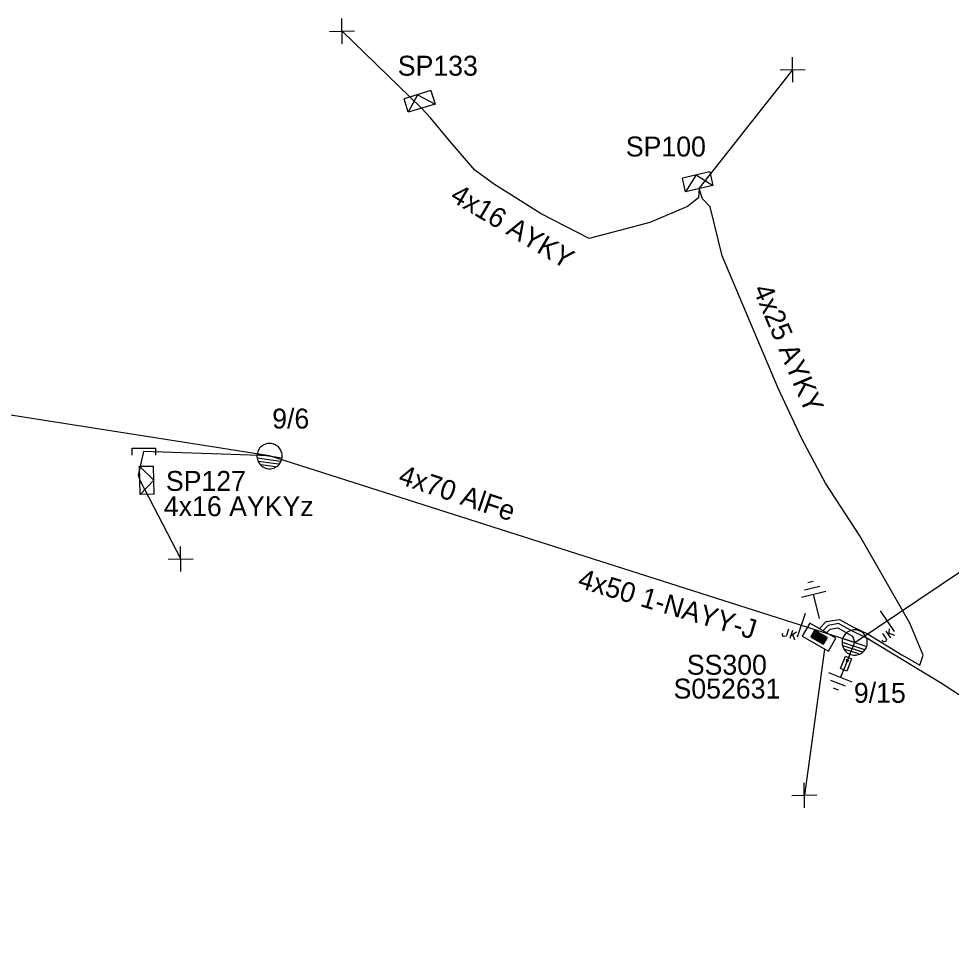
# Model space of a CAD drawing. Extents: x -762504 to -761250, y -1152974 to -1152253.
# Drawn here: x -761400.94 to -761354.44, y -1152566.54 to -1152520.81 of the extents above; entities that cross this region are included whole.
import ezdxf

# ---------------------------------------------------------------- set-up
doc = ezdxf.new("R2010")
doc.units = 0
for name, color, linetype in [('Vrstva 1', 7, 'Continuous'), ('Vrstva 12', 7, 'Continuous'), ('Vrstva 13', 7, 'Continuous'), ('Vrstva 15', 7, 'Continuous'), ('Vrstva 16', 7, 'Continuous'), ('Vrstva 18', 7, 'Continuous'), ('Vrstva 2', 7, 'Continuous'), ('Vrstva 28', 7, 'Continuous'), ('Vrstva 29', 7, 'Continuous'), ('Vrstva 30', 7, 'Continuous'), ('Vrstva 31', 7, 'Continuous'), ('Vrstva 33', 7, 'Continuous'), ('Vrstva 34', 7, 'Continuous'), ('Vrstva 5', 7, 'Continuous'), ('Vrstva 52', 7, 'Continuous'), ('Vrstva 54', 7, 'Continuous'), ('Vrstva 55', 7, 'Continuous'), ('Vrstva 59', 7, 'Continuous'), ('Vrstva 6', 7, 'Continuous')]:
    doc.layers.add(name, color=color, linetype=linetype)

msp = doc.modelspace()

# ---------------------------------------------------------------- linework, layer by layer
at = {"layer": 'Vrstva 1'}
msp.add_lwpolyline([(-761359.26, -1152551.93), (-761388.43, -1152542.63), (-761419.76, -1152537.7), (-761438.71, -1152534.5), (-761457.83, -1152530.5)], dxfattribs=at)
at = {"layer": 'Vrstva 13'}
for points in [[(-761395.3, -1152542.234), (-761394.119, -1152542.234)], [(-761395.3, -1152542.234), (-761395.3, -1152542.588)], [(-761394.119, -1152542.234), (-761394.119, -1152542.588)], [(-761387.805, -1152542.722), (-761387.8, -1152542.656), (-761387.801, -1152542.59), (-761387.809, -1152542.525), (-761387.824, -1152542.461), (-761387.845, -1152542.398), (-761387.873, -1152542.339), (-761387.907, -1152542.282), (-761387.946, -1152542.229), (-761387.991, -1152542.181), (-761388.041, -1152542.138), (-761388.095, -1152542.1), (-761388.153, -1152542.068), (-761388.214, -1152542.042), (-761388.277, -1152542.023), (-761388.342, -1152542.011), (-761388.407, -1152542.005), (-761388.473, -1152542.006), (-761388.539, -1152542.014), (-761388.603, -1152542.029), (-761388.665, -1152542.05), (-761388.725, -1152542.078), (-761388.781, -1152542.112), (-761388.834, -1152542.152), (-761388.882, -1152542.197), (-761388.925, -1152542.247), (-761388.963, -1152542.3), (-761388.995, -1152542.358), (-761389.021, -1152542.419), (-761389.04, -1152542.482), (-761389.053, -1152542.547), (-761389.059, -1152542.612), (-761389.058, -1152542.678), (-761389.05, -1152542.744), (-761389.035, -1152542.808), (-761389.013, -1152542.87), (-761388.985, -1152542.93), (-761388.951, -1152542.987), (-761388.912, -1152543.039), (-761388.867, -1152543.087), (-761388.817, -1152543.131), (-761388.763, -1152543.169), (-761388.705, -1152543.2), (-761388.645, -1152543.226), (-761388.581, -1152543.246), (-761388.517, -1152543.258), (-761388.451, -1152543.264), (-761388.385, -1152543.263), (-761388.32, -1152543.255), (-761388.255, -1152543.24), (-761388.193, -1152543.218), (-761388.133, -1152543.191), (-761388.077, -1152543.157), (-761388.024, -1152543.117), (-761387.976, -1152543.072), (-761387.933, -1152543.022), (-761387.895, -1152542.968), (-761387.863, -1152542.91), (-761387.837, -1152542.85), (-761387.818, -1152542.787), (-761387.805, -1152542.722)], [(-761389.054, -1152542.542), (-761387.807, -1152542.718)], [(-761389.05, -1152542.722), (-761387.89, -1152542.885)], [(-761388.982, -1152542.88), (-761387.979, -1152543.022)], [(-761388.866, -1152543.046), (-761388.145, -1152543.147)], [(-761358.661, -1152552.129), (-761358.644, -1152552.065), (-761358.633, -1152552), (-761358.63, -1152551.934), (-761358.633, -1152551.868), (-761358.644, -1152551.803), (-761358.661, -1152551.74), (-761358.684, -1152551.678), (-761358.714, -1152551.619), (-761358.75, -1152551.564), (-761358.792, -1152551.513), (-761358.838, -1152551.466), (-761358.89, -1152551.425), (-761358.945, -1152551.389), (-761359.004, -1152551.359), (-761359.065, -1152551.335), (-761359.129, -1152551.318), (-761359.194, -1152551.308), (-761359.26, -1152551.304), (-761359.326, -1152551.308), (-761359.391, -1152551.318), (-761359.454, -1152551.335), (-761359.516, -1152551.359), (-761359.575, -1152551.389), (-761359.63, -1152551.425), (-761359.681, -1152551.466), (-761359.728, -1152551.513), (-761359.769, -1152551.564), (-761359.805, -1152551.619), (-761359.835, -1152551.678), (-761359.859, -1152551.74), (-761359.876, -1152551.803), (-761359.886, -1152551.868), (-761359.89, -1152551.934), (-761359.886, -1152552), (-761359.876, -1152552.065), (-761359.859, -1152552.129), (-761359.835, -1152552.19), (-761359.805, -1152552.249), (-761359.769, -1152552.305), (-761359.728, -1152552.356), (-761359.681, -1152552.403), (-761359.63, -1152552.444), (-761359.575, -1152552.48), (-761359.516, -1152552.51), (-761359.455, -1152552.533), (-761359.391, -1152552.551), (-761359.326, -1152552.561), (-761359.26, -1152552.564), (-761359.194, -1152552.561), (-761359.129, -1152552.551), (-761359.065, -1152552.533), (-761359.003, -1152552.51), (-761358.945, -1152552.48), (-761358.89, -1152552.444), (-761358.838, -1152552.402), (-761358.792, -1152552.356), (-761358.75, -1152552.305), (-761358.714, -1152552.249), (-761358.684, -1152552.191), (-761358.661, -1152552.129)], [(-761359.886, -1152551.913), (-761358.772, -1152552.275)], [(-761359.859, -1152551.735), (-761358.661, -1152552.125)], [(-761359.848, -1152552.081), (-761358.883, -1152552.394)], [(-761359.762, -1152552.264), (-761359.069, -1152552.489)]]:
    msp.add_lwpolyline(points, dxfattribs=at)
at = {"layer": 'Vrstva 15'}
for points in [[(-761361.592, -1152548.943), (-761361.463, -1152548.911)], [(-761361.463, -1152548.911), (-761361.338, -1152548.88)], [(-761361.918, -1152549.668), (-761360.705, -1152549.366)], [(-761361.759, -1152549.309), (-761360.995, -1152549.118)], [(-761361.009, -1152550.73), (-761361.311, -1152549.517)], [(-761359.496, -1152552.525), (-761359.964, -1152553.684)], [(-761359.385, -1152553.918), (-761360.544, -1152553.45)], [(-761359.724, -1152554.115), (-761360.455, -1152553.82)], [(-761360.198, -1152554.263), (-761360.317, -1152554.215)], [(-761360.075, -1152554.313), (-761360.198, -1152554.263)]]:
    msp.add_lwpolyline(points, dxfattribs=at)
at = {"layer": 'Vrstva 16'}
for points in [[(-761359.261, -1152551.925), (-761359.655, -1152552.902)], [(-761359.965, -1152553.233), (-761359.717, -1152552.622)], [(-761359.717, -1152552.622), (-761359.412, -1152552.745)], [(-761359.655, -1152552.902), (-761359.664, -1152552.766)], [(-761359.412, -1152552.745), (-761359.659, -1152553.357)], [(-761359.655, -1152552.902), (-761359.555, -1152552.81)], [(-761359.659, -1152553.357), (-761359.965, -1152553.233)], [(-761359.814, -1152553.294), (-761359.963, -1152553.664)]]:
    msp.add_lwpolyline(points, dxfattribs=at)
at = {"layer": 'Vrstva 18'}
for points in [[(-761361.736, -1152550.482), (-761362.123, -1152551.671)], [(-761357.984, -1152550.345), (-761357.285, -1152551.381)], [(-761362.861, -1152551.571), (-761362.858, -1152551.514)], [(-761362.801, -1152551.626), (-761362.861, -1152551.571)], [(-761362.858, -1152551.514), (-761362.843, -1152551.468)], [(-761362.773, -1152551.635), (-761362.801, -1152551.626)], [(-761362.697, -1152551.624), (-761362.773, -1152551.635)], [(-761362.662, -1152551.578), (-761362.697, -1152551.624)], [(-761362.561, -1152551.269), (-761362.662, -1152551.578)], [(-761362.365, -1152551.333), (-761362.493, -1152551.727)], [(-761362.444, -1152551.577), (-761362.168, -1152551.397)], [(-761362.353, -1152551.518), (-761362.263, -1152551.801)], [(-761357.871, -1152551.48), (-761357.69, -1152551.749)], [(-761357.7, -1152551.364), (-761357.469, -1152551.707)], [(-761357.557, -1152551.576), (-761357.528, -1152551.249)], [(-761357.546, -1152551.468), (-761357.269, -1152551.572)], [(-761357.861, -1152551.865), (-761357.888, -1152551.824)], [(-761357.818, -1152551.901), (-761357.861, -1152551.865)], [(-761357.738, -1152551.889), (-761357.818, -1152551.901)], [(-761357.713, -1152551.872), (-761357.738, -1152551.889)], [(-761357.676, -1152551.805), (-761357.713, -1152551.872)], [(-761357.69, -1152551.749), (-761357.676, -1152551.805)]]:
    msp.add_lwpolyline(points, dxfattribs=at)
at = {"layer": 'Vrstva 28'}
for points in [[(-761361.496, -1152550.973), (-761361.871, -1152551.623)], [(-761360.197, -1152551.723), (-761361.496, -1152550.973)], [(-761361.871, -1152551.623), (-761360.572, -1152552.373)], [(-761361.265, -1152551.318), (-761361.454, -1152551.645)], [(-761361.454, -1152551.645), (-761360.81, -1152552.017)], [(-761361.248, -1152551.382), (-761361.389, -1152551.628)], [(-761361.389, -1152551.628), (-761360.827, -1152551.953)], [(-761361.23, -1152551.447), (-761361.325, -1152551.611)], [(-761361.325, -1152551.611), (-761360.844, -1152551.888)], [(-761360.621, -1152551.69), (-761361.265, -1152551.318)], [(-761361.213, -1152551.511), (-761361.26, -1152551.593)], [(-761361.26, -1152551.593), (-761360.861, -1152551.824)], [(-761360.685, -1152551.707), (-761361.248, -1152551.382)], [(-761360.75, -1152551.724), (-761361.23, -1152551.447)], [(-761360.814, -1152551.742), (-761361.213, -1152551.511)], [(-761361.201, -1152551.573), (-761360.874, -1152551.762)], [(-761360.81, -1152552.017), (-761360.621, -1152551.69)], [(-761360.861, -1152551.824), (-761360.814, -1152551.742)], [(-761360.844, -1152551.888), (-761360.75, -1152551.724)], [(-761360.827, -1152551.953), (-761360.685, -1152551.707)], [(-761360.572, -1152552.373), (-761360.197, -1152551.723)]]:
    msp.add_lwpolyline(points, dxfattribs=at)
at = {"layer": 'Vrstva 31'}
for points in [[(-761380.383, -1152524.405), (-761381.721, -1152524.814)], [(-761380.383, -1152524.405), (-761380.178, -1152525.074), (-761381.517, -1152525.483), (-761381.721, -1152524.814)], [(-761381.052, -1152524.609), (-761381.517, -1152525.483)], [(-761381.052, -1152524.609), (-761380.178, -1152525.074)], [(-761366.483, -1152528.449), (-761367.847, -1152528.764)], [(-761366.483, -1152528.449), (-761366.325, -1152529.132), (-761367.689, -1152529.446), (-761367.847, -1152528.764)], [(-761367.165, -1152528.607), (-761367.689, -1152529.446)], [(-761367.165, -1152528.607), (-761366.325, -1152529.132)], [(-761394.187, -1152544.531), (-761394.887, -1152544.543), (-761394.912, -1152543.143), (-761394.212, -1152543.131)], [(-761394.2, -1152543.831), (-761394.912, -1152543.143)], [(-761394.187, -1152544.531), (-761394.212, -1152543.131)], [(-761394.2, -1152543.831), (-761394.887, -1152544.543)]]:
    msp.add_lwpolyline(points, dxfattribs=at)
at = {"layer": 'Vrstva 34'}
for points in [[(-761384.809, -1152522.065), (-761384.831, -1152520.815)], [(-761385.445, -1152521.451), (-761384.195, -1152521.429)], [(-761362.339, -1152523.985), (-761362.361, -1152522.735)], [(-761362.975, -1152523.371), (-761361.725, -1152523.349)], [(-761392.849, -1152548.395), (-761392.871, -1152547.145)], [(-761393.485, -1152547.781), (-761392.235, -1152547.759)], [(-761361.759, -1152560.175), (-761361.781, -1152558.925)], [(-761362.395, -1152559.561), (-761361.145, -1152559.539)]]:
    msp.add_lwpolyline(points, dxfattribs=at)
at = {"layer": 'Vrstva 5'}
for points in [[(-761361.03, -1152551.25), (-761360.69, -1152550.89), (-761360.02, -1152550.78), (-761359.38, -1152551.14), (-761358.59, -1152551.52), (-761356.91, -1152552.54), (-761356.02, -1152553.06), (-761355.84, -1152552.57), (-761356.51, -1152550.96), (-761359.01, -1152546.61), (-761360.71, -1152543.98), (-761361.9, -1152541.78), (-761363.09, -1152539.21), (-761365.87, -1152532.64), (-761366.47, -1152530.2), (-761366.84, -1152529.81), (-761367.01, -1152529.29)], [(-761337.55, -1152566.54), (-761337.18, -1152565.94), (-761337.31, -1152565.5), (-761339.55, -1152564), (-761343.34, -1152561.5), (-761347.98, -1152558.48), (-761354.99, -1152553.94), (-761358.69, -1152551.7), (-761359.47, -1152551.32), (-761360.06, -1152550.99), (-761360.59, -1152551.08), (-761360.85, -1152551.35)], [(-761360.67, -1152551.45), (-761360.49, -1152551.27), (-761360.1, -1152551.2), (-761359.37, -1152551.61), (-761359.26, -1152551.93)]]:
    msp.add_lwpolyline(points, dxfattribs=at)
at = {"layer": 'Vrstva 52'}
for points in [[(-761367.01, -1152529.29), (-761367.05, -1152529.76), (-761367.59, -1152530.18), (-761369.47, -1152530.99), (-761372.49, -1152531.78), (-761374.89, -1152530.55), (-761377.27, -1152529.05), (-761378.19, -1152528.38), (-761379.53, -1152526.82), (-761380.41, -1152525.76), (-761380.85, -1152525.28)], [(-761359.26, -1152551.93), (-761336.11, -1152536.37)]]:
    msp.add_lwpolyline(points, dxfattribs=at)
at = {"layer": 'Vrstva 54'}
msp.add_lwpolyline([(-761388.43, -1152542.63), (-761394.71, -1152542.41), (-761394.98, -1152543.58), (-761394.9, -1152543.84)], dxfattribs=at)
at = {"layer": 'Vrstva 59'}
for points in [[(-761380.85, -1152525.28), (-761384.82, -1152521.44)], [(-761367.01, -1152529.29), (-761362.35, -1152523.36)], [(-761394.9, -1152543.84), (-761392.86, -1152547.77)], [(-761360.76, -1152552.27), (-761361.77, -1152559.55)]]:
    msp.add_lwpolyline(points, dxfattribs=at)

# ---------------------------------------------------------------- texts
at = {"layer": 'Vrstva 12'}
for s, p in [('9/6', (-761388.3, -1152541.26)), ('9/15', (-761359.3, -1152554.94))]:
    msp.add_text(s, height=0.9943, dxfattribs=at).set_placement(p)
at = {"layer": 'Vrstva 2'}
msp.add_text('4x70 AlFe', height=0.9943, rotation=341.4108, dxfattribs=at).set_placement((-761382.07, -1152543.99))
at = {"layer": 'Vrstva 29'}
msp.add_text('S052631', height=0.9943, dxfattribs=at).set_placement((-761368.29, -1152554.73))
at = {"layer": 'Vrstva 30'}
msp.add_text('SS300', height=0.9943, dxfattribs=at).set_placement((-761367.63, -1152553.54))
at = {"layer": 'Vrstva 33'}
for s, p in [('SP133', (-761382.04, -1152523.66)), ('SP100', (-761370.67, -1152527.69)), ('SP127', (-761393.6, -1152544.37))]:
    msp.add_text(s, height=0.9943, dxfattribs=at).set_placement(p)
at = {"layer": 'Vrstva 54'}
msp.add_text('4x16 AYKY', height=0.9943, rotation=329.2208, dxfattribs=at).set_placement((-761379.49, -1152529.86))
at = {"layer": 'Vrstva 55'}
msp.add_text('4x16 AYKYz', height=0.9943, dxfattribs=at).set_placement((-761393.7, -1152545.63))
at = {"layer": 'Vrstva 6'}
for s, height, rotation, p in [('4x25 AYKY', 0.9943, 293.0646, (-761364.35, -1152534.31)), ('4x50 1-NAYY-J', 0.99429, 343.4312, (-761373.12, -1152549.18))]:
    msp.add_text(s, height=height, rotation=rotation, dxfattribs=at).set_placement(p)

doc.saveas('drawing.dxf')
